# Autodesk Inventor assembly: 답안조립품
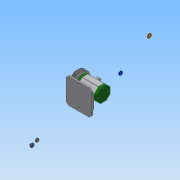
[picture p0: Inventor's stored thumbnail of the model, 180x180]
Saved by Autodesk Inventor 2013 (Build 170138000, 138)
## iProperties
Created: 2018-06
Part Number: 답안조립품
Document SubType Name: Assembly
Designer: Administrator
Author: Administrator
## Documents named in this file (16)
- C:\Users\Administrator\Desktop\480608V1011\답안조립품.iam
- C:\Users\Administrator\Desktop\480608V1011\V벨트풀리.ipt
- C:\Users\Administrator\Desktop\480608V1011\고무캡.ipt
- C:\Users\Administrator\Desktop\480608V1011\너트 M8.ipt
- 너트 M8.ipt
- C:\Users\Administrator\Desktop\480608V1011\뒤커버.ipt
- C:\Users\Administrator\Desktop\480608V1011\베어링 15x32x9.ipt
- C:\Users\Administrator\Desktop\480608V1011\본체.ipt
- C:\Users\Administrator\Desktop\480608V1011\볼트 M4x12.ipt
- C:\Users\Administrator\Desktop\480608V1011\스프링와셔 8.ipt
- C:\Users\Administrator\Desktop\480608V1011\앞커버.ipt
- C:\Users\Administrator\Desktop\480608V1011\오일 실 15 25 7.ipt
- C:\Users\Administrator\Desktop\480608V1011\와셔 8x17.ipt
- C:\Users\Administrator\Desktop\480608V1011\축.ipt
- C:\Users\Administrator\Desktop\480608V1011\키 3x3x12.ipt
- 키 3x3x12.ipt
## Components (2 placed, 2 different names)
1. V벨트풀리:1
2. 고무캡:1
